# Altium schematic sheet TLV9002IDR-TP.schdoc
size 127 x 101 mm
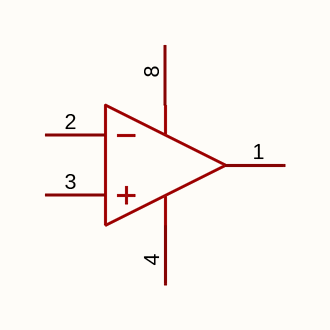
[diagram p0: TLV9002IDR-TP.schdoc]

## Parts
U?  tlv9002idr-tp  [SOP-8_L4.9-W3.9-P1.27-LS6.0-BL]  (value not drawn)  (part A of 2)

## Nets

Not connected (* = marked no-connect by the designer): U? 1(OUTA) 2(INA-) 3(INA+) 4(-V) 8(+V)

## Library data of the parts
U? = tlv9002idr-tp: 放大器数:2;轨到轨:轨到轨输入,轨到轨输出;增益带宽积(GBW):1MHz;输入失调电压(Vos):5mV;压摆率(SR):-;输入偏置电流(Ib):10pA;; Manufacturer: TECH PUBLIC(台舟); AddInBom: yes; ModelId: 75c24a7891ee4dd6bdac16a7163ff87e; ModelName: SOP-8_L4.9-W3.9-P1.27-LS6.0-BL-1; ModelTransform: 192.913,236.22,0,0,0,0,-0.393,2.749,0; Number of Channels: 2; Maximum Power Supply Range (Vdd-Vss): 7V; Gain Bandwidth Product: 1MHz; Vos - Input Offset Voltage: 5mV; Input Offset Voltage Drift(Vos TC): 650nV/℃; Ib - Input Bias Current: 10pA; Common Mode Rejection Ratio(CMRR): 95dB; Quiescent Current: 50uA; Output Current: 20mA; Single supply: 2.1V~5.5V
